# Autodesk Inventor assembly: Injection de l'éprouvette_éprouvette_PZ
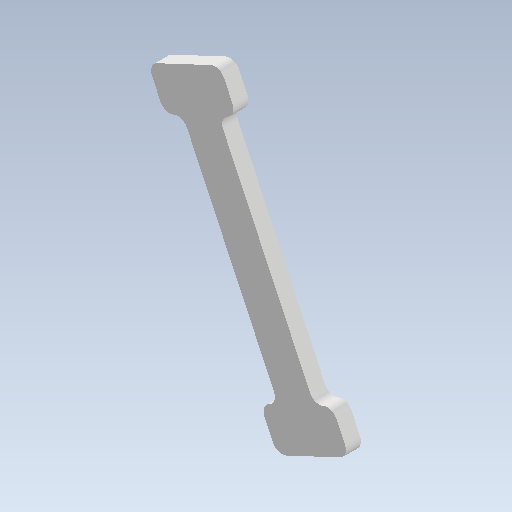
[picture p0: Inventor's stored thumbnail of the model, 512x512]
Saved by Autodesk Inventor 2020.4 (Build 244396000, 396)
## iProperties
Created: 2021-10
Part Number: Injection de l'éprouvette_éprouvette_PZ
Document SubType Name: Assembly
Designer: mel
Author: mel
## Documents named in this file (2)
- D:\travail\année 2020-2021\itec\prépa injection plastique eduscol\dossier de travail\Ensemble des pièces de l'activité\Conception de moule1\Injection de l'éprouvette_éprouvette_PZ.iam
- D:\travail\année 2020-2021\itec\prépa injection plastique eduscol\dossier de travail\Ensemble des pièces de l'activité\Conception de moule1\Injection de l'éprouvette_éprouvette_MP.ipt
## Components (1 placed, 1 different names)
1. Injection de l'éprouvette_éprouvette_MP:1 — Affleurement:1, Affleurement:2, Affleurement:3
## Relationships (3: Flush 3)
- Affleurement:1 [Flush]: Injection de l'éprouvette_éprouvette_MP:1
- Affleurement:2 [Flush]: Injection de l'éprouvette_éprouvette_MP:1
- Affleurement:3 [Flush]: Injection de l'éprouvette_éprouvette_MP:1
